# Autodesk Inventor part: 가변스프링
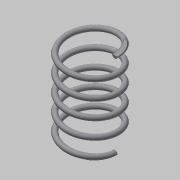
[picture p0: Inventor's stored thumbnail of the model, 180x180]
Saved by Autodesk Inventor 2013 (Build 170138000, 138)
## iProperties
Created: 2019-05
Part Number: 가변스프링
Material: 일반
Document SubType Name: Modeling
Designer: Administrator
Density: 1 g/cm^3
Mass: 0.973069 g
Surface Area: 19.733 cm^2
Volume: 0.973069 cm^3
Author: Administrator
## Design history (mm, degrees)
sketch "스케치1"
  geometry: L1 (0, 0)-(10, 0); L2 (10, 0)-(10, 34); L3 (10, 34)-(0, 34); L4 (0, 34)-(0, 0); C1 r 1 at (10, 0)
  constraints: 8 end point, 2 parallel, 1 centre point, 1 coincident, 1 horizontal, 1 perpendicular
  dimensions: "d0" = 2 diameter of C1; "d1" = 20 diameter of L2 L4; "d2" = 34 distance of L1.end L2.end (derived)
feature "코일1" sketch "스케치1" pitch "d3" = 10; turns "d5" = 5; dims "d4" = 34 (= d2), "d6" = 0, angle "d7" = 90 deg, angle "d8" = 90 deg, "d9" = 0, "d10" = 0
sketch "스케치3"
  geometry: L1 (34, 12)-(0, 12); L2 (0, 12)-(0, -12); L3 (0, -12)-(34, -12); L4 (34, -12)-(34, 12); 2 further points
  constraints: 8 end point, 2 parallel, 1 coincident, 1 horizontal, 1 midpoint, 1 perpendicular
  dimensions: "d11" = 34 distance of L2.end L3.end (derived); "d13" = 24 distance of L3.end L1.start
extrude "돌출1" sketch "스케치3" stored distance "d14" = 24; taper "d15" = 0 deg
node "솔리드1"
